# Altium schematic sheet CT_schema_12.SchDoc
size 145 x 119 mm
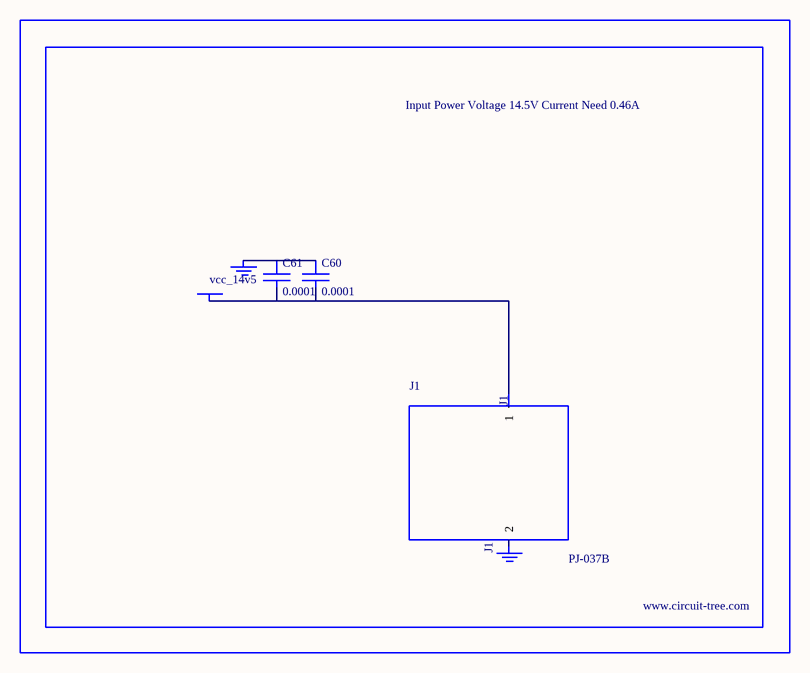
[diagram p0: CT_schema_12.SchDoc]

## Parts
BORDER11  (no value)
C60  0.0001  [EXV-9H]
C61  0.0001  [EXV-9H]
GND_INSTANCE_11_0  (no value)
GND_INSTANCE_11_1  (no value)
J1  PJ-037B  [PJ-037B_PACKAGE]
POWER_INSTANCE_11_0  vcc_14v5

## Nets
NetC60_1: C60.1 C61.1 GND_INSTANCE_11_0.0(GND)
NetC60_2: C60.2 C61.2 J1.1 POWER_INSTANCE_11_0.0(PWR)

Not connected (* = marked no-connect by the designer): GND_INSTANCE_11_1 0(GND); J1 2

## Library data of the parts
BORDER11 = BORDER_PAGE11
C60 C61 = EDK107M035A9HAA
GND_INSTANCE_11_0 GND_INSTANCE_11_1 = GND
POWER_INSTANCE_11_0 = PWR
